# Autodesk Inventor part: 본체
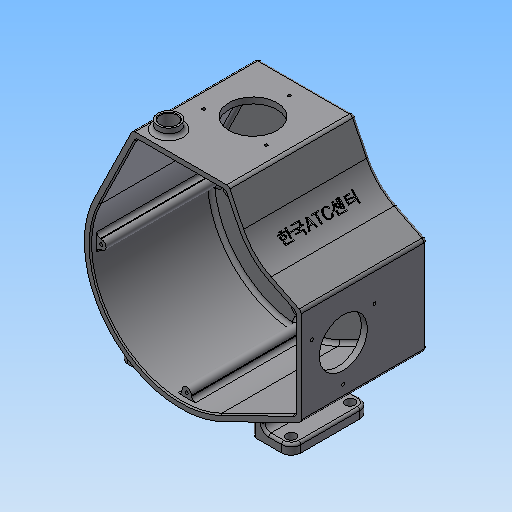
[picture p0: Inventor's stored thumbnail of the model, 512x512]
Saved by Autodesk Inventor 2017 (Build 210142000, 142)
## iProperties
Created: 2017-05
Part Number: 본체
Material: 일반
Document SubType Name: Modeling
Designer: mduedu
Density: 1 g/cm^3
Appearance: 기본값
Mass: 496.576 g
Surface Area: 1824.08 cm^2
Volume: 496.576 cm^3
Author: mduedu
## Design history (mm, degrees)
sketch "스케치1"
  geometry: L1 (-71.801, 35.28)-(-40, 100); L2 (-40, 100)-(40, 100); L3 (40, 100)-(59.768, 59.768); L4 (59.768, 59.768)-(100, 40); L5 (100, 40)-(100, -40); L6 (100, -40)-(35.28, -71.801); A1 r 80 centre (0, 0) between (-71.801, 35.28) and (35.28, -71.801); 3 further points
  constraints: 12 end point, 4 tangent, 2 midpoint, 2 point on circle, 1 centre point, 1 coincident, 1 horizontal, 1 horizontal alignment, 1 perpendicular, 1 vertical alignment
  dimensions: "d0" = 160 diameter of A1; "d2" = 100 distance from line of L2 point (0, 0); "d3" = 100 distance from line of L5 point (0, 0); "d4" = 80 distance of L1.end L2.end; "d5" = 80 distance of L4.end L5.end
extrude "돌출1" new body sketch "스케치1" distance "d6" = 5; taper "d7" = 0 deg
fillet "모깎기1" dims "d8" = 50
sketch "스케치2"
  geometry: C1 r 22 at (0, 0); 1 further point
  constraints: 1 centre point, 1 coincident
  dimensions: "d9" = 44 diameter of C1
extrude "돌출2" join sketch "스케치2" distance "d10" = 22.5; taper "d11" = 0 deg
sketch "스케치3"
  geometry: C1 r 18.5 at (0, 0); 1 further point
  constraints: 1 centre point, 1 coincident
  dimensions: "d12" = 37 diameter of C1
extrude "돌출3" cut sketch "스케치3" distance "d13" = 9; taper "d14" = 0 deg
fillet "모깎기2" dims "d15" = 3
sketch "스케치4"
  geometry: L1 (35.28, -71.801)-(100, -40) reference; L2 (100, -40)-(100, 40) reference; L3 (100, 40)-(75.073, 52.248) reference; L4 (52.248, 75.073)-(40, 100) reference; L5 (40, 100)-(-40, 100) reference; L6 (-40, 100)-(-71.801, 35.28) reference; L7 (-36.886, 95)-(36.886, 95); L8 (36.886, 95)-(47.76, 72.868); L9 (72.868, 47.76)-(95, 36.886); L10 (95, 36.886)-(95, -36.886); L11 (95, -36.886)-(33.075, -67.313); L12 (-67.313, 33.075)-(-36.886, 95); C1 r 25 at (0, 0) reference; A1 r 50 centre (97.123, 97.123) between (52.248, 75.073) and (75.073, 52.248) reference; A2 r 80 centre (0, 0) between (-71.801, 35.28) and (35.28, -71.801) reference; A3 r 55 centre (97.123, 97.123) between (47.76, 72.868) and (72.868, 47.76); A4 r 75 centre (0, 0) between (-67.313, 33.075) and (33.075, -67.313); 1 further point
  constraints: 12 end point, 4 point on circle, 2 centre point, 7 other
  dimensions: "d16" = 5 distance between parallel lines of L7 L5
extrude "돌출4" join sketch "스케치4" distance "d17" = 100; taper "d18" = 0 deg
sketch "스케치5"
  geometry: L1 (80, 0)-(0, 0) reference; C1 r 20 at (40, -45); 2 further points
  constraints: 1 centre point, 1 midpoint, 1 vertical alignment
  dimensions: "d19" = 40 diameter of C1; "d21" = 45 distance from line of C1.centre L1
extrude "돌출5" cut sketch "스케치5" stored distance "d22" = 100; taper "d23" = 0 deg
sketch "스케치6"
  geometry: L1 (0, 0)-(0, -105) reference; L2 (80, -105)-(0, -105) reference; C1 r 9 at (14, -89); 1 further point
  constraints: 1 centre point
  dimensions: "d24" = 18 diameter of C1; "d26" = 14 distance from line of C1.centre L1; "d27" = 16 distance from line of C1.centre L2
extrude "돌출6" join sketch "스케치6" distance "d28" = 7; taper "d29" = 0 deg
hole "구멍1" diameter "d32" = 14; stored, may be unused: countersink angle "d36" = 90 deg, drill point angle "d38" = 118 deg; dims "d33" = 6, "d34" = 4, "d35" = 2, "d37" = 8, "d39" = 10, "d40" = 10
sketch "스케치7"
  geometry: L1 (-105, 0)-(-105, 80) reference; L2 (0, 0)-(0, 80) reference; C1 r 20 at (-70, 40); 2 further points
  constraints: 1 centre point, 1 horizontal alignment, 1 midpoint
  dimensions: "d41" = 40 diameter of C1; "d42" = 35 distance from line of C1.centre L1
extrude "돌출7" cut sketch "스케치7" stored distance "d43" = 7; taper "d44" = 0 deg
node "작업 평면1"
sketch "스케치8"
  geometry: L1 (47.76, 72.868)-(36.886, 95) reference; L2 (36.886, 95)-(-36.886, 95) reference; L3 (-36.886, 95)-(-67.313, 33.075) reference; L4 (33.075, -67.313)-(95, -36.886) reference; L5 (95, -36.886)-(95, 36.886) reference; L6 (95, 36.886)-(72.868, 47.76) reference; L7 (95, 36.886)-(95, -36.886) reference; L8 (-36.886, 95)-(36.886, 95) reference; L9 (36.886, 95)-(47.76, 72.868) reference; L10 (-71, 4)-(-74.893, 4); L11 (-71, -4)-(-74.893, -4); L12 (-4, -71)-(-4, -74.893); L13 (4, -71)-(4, -74.893); L14 (30.394, 91)-(30.394, 95); L15 (34.394, 87)-(40.817, 87); L16 (30.394, 95)-(36.886, 95); L17 (36.886, 95)-(37.984, 92.764); L18 (91, 30.394)-(95, 30.394); L19 (87, 34.394)-(87, 40.817); L20 (87, 40.817)-(95, 36.886); L21 (95, 36.886)-(95, 30.394); C1 r 25 at (0, 0) reference; A1 r 75 centre (0, 0) between (-67.313, 33.075) and (33.075, -67.313) reference; A2 r 55 centre (97.123, 97.123) between (47.76, 72.868) and (72.868, 47.76) reference; A3 r 4 centre (-71, 0) between (-71, 4) and (-71, -4); A4 r 4 centre (0, -71) between (-4, -71) and (4, -71); A5 r 4 centre (34.394, 91) between (30.394, 91) and (34.394, 87); A6 r 75 centre (0, 0) between (-67.313, 33.075) and (33.075, -67.313) reference; A7 r 4 centre (91, 34.394) between (91, 30.394) and (87, 34.394); 1 further point
  constraints: 24 end point, 17 point on circle, 14 tangent, 5 point on line, 4 centre point, 3 equal radius, 3 perpendicular, 3 vertical, 2 collinear, 2 horizontal, 1 horizontal alignment, 1 parallel, 1 vertical alignment
  dimensions: "d46" = 8 diameter of A3
extrude "돌출8" join sketch "스케치8" stored distance "d49" = 7; taper "d50" = 0 deg
node "작업 평면2"
sketch "스케치9"
  geometry: L1 (71.801, 0)-(71.801, 105) reference; L2 (71.801, 0)-(-35.28, 0) reference; L3 (-35.28, 0)-(-35.28, 105) reference; L4 (71.801, 105)-(-35.28, 105) reference; L5 (40, 0)-(40, 105) reference; L6 (71.801, 52.5)-(-35.28, 52.5); L7 (71.801, 20)-(40, 20); L8 (40, 20)-(40, 85); L9 (40, 85)-(71.801, 85); L10 (71.801, 85)-(71.801, 20); 1 further point
  constraints: 10 end point, 2 midpoint, 2 parallel, 2 point on line, 1 horizontal, 1 perpendicular, 1 other
  dimensions: "d52" = 20 distance between parallel lines of L7 L2
extrude "돌출9" join sketch "스케치9" distance "d53" = 8; taper "d54" = 0 deg
fillet "모깎기3" dims "d55" = 8
sketch "스케치10"
  geometry: C1 r 4 at (-63.801, -28); C2 r 4 at (-63.801, -77); A1 r 8 centre (-63.801, -28) between (-63.801, -20) and (-71.801, -28) reference; A2 r 8 centre (-63.801, -77) between (-71.801, -77) and (-63.801, -85) reference; 1 further point
  constraints: 2 centre point, 2 coincident, 1 equal radius
  dimensions: "d56" = 8 diameter of C1
extrude "돌출10" cut sketch "스케치10" stored distance "d57" = 50.5; taper "d58" = 0 deg
sketch "스케치11"
  geometry: L1 (-63.801, -20)-(-40, -20) reference; L2 (-40, -20)-(-40, -85) reference; L3 (-40, -85)-(-63.801, -85) reference; L4 (-71.801, -77)-(-71.801, -28) reference; L5 (71.801, -77)-(71.801, -28) reference; L6 (40, -85)-(63.801, -85) reference; L7 (40, -20)-(40, -85) reference; L8 (63.801, -20)-(40, -20) reference; L9 (-40, -85)-(-48, -85); L10 (-48, -85)-(-48, -20); L11 (-48, -20)-(-40, -20); L12 (-40, -20)-(-40, -85); L13 (40, -85)-(48, -85); L14 (48, -85)-(48, -20); L15 (48, -20)-(40, -20); L16 (40, -20)-(40, -85); C1 r 4 at (-63.801, -28) reference; C2 r 4 at (-63.801, -77) reference; C3 r 4 at (63.801, -28) reference; C4 r 4 at (63.801, -77) reference; A1 r 8 centre (-63.801, -28) between (-63.801, -20) and (-71.801, -28) reference; A2 r 8 centre (-63.801, -77) between (-71.801, -77) and (-63.801, -85) reference; A3 r 8 centre (63.801, -28) between (71.801, -28) and (63.801, -20) reference; A4 r 8 centre (63.801, -77) between (63.801, -85) and (71.801, -77) reference; 1 further point
  constraints: 16 end point, 4 parallel, 2 horizontal, 2 perpendicular, 2 point on line
  dimensions: "d59" = 8 distance of L10.end L11.end; "d61" = 8 distance of L14.end L15.end
extrude "돌출11" join sketch "스케치11" stored distance "d62" = 5; taper "d63" = 0 deg
fillet "모깎기4" dims "d64" = 5
fillet "모깎기5" dims "d65" = 2
fillet "모깎기6" dims "d66" = 2
fillet "모깎기8" dims "d68" = 2
fillet "모깎기9" dims "d70" = 3, "d101" = 1
fillet "모깎기10" dims "d71" = 3
fillet "모깎기11" dims "d72" = 3
fillet "모깎기12" dims "d73" = 3
fillet "모깎기13" dims "d76" = 3
chamfer "모따기1" distance "d77" = 0.5; stored, may be unused: second distance "d78" = 2, angle "d79" = 45 deg
chamfer "모따기2" distance "d87" = 1; stored, may be unused: second distance "d88" = 2, angle "d89" = 45 deg
chamfer "모따기3" distance "d90" = 1; stored, may be unused: second distance "d91" = 2, angle "d92" = 45 deg
sketch "스케치14"
  geometry: 3 further points
  constraints: 3 other
hole "구멍2" sketch "스케치14" at (-55.375, -40), (-3.414, -40), (-29.394, -85) diameter "d93" = 2.459; stored, may be unused: countersink angle "d97" = 90 deg, drill point angle "d99" = 0 deg; dims "d94" = 6, "d95" = 4, "d96" = 2, "d98" = 8
sketch "스케치15"
  geometry: 3 further points
  constraints: 3 other
hole "구멍4" sketch "스케치15" at (-55.981, -14.394), (-4.019, -14.394), (-30, -59.394) diameter "d102" = 2.459; stored, may be unused: countersink angle "d106" = 90 deg, drill point angle "d108" = 0 deg; dims "d103" = 6, "d104" = 4, "d105" = 2, "d107" = 8
sketch "스케치16"
  geometry: 4 further points
  constraints: 4 other
hole "구멍6" sketch "스케치16" at (0, -71), (91, 34.394), (34.394, 91), (-71, 0) diameter "d109" = 2.459; stored, may be unused: countersink angle "d113" = 90 deg, drill point angle "d115" = 120 deg; dims "d110" = 8.5, "d111" = 4, "d112" = 2, "d114" = 10
node "작업 평면4"
sketch "스케치17"
  geometry: 2 further points
  constraints: 1 horizontal alignment, 1 other
  dimensions: "d116" = 52.5 distance of point (0, 16.14) point (52.5, 16.14)
feature "엠보싱2" sketch "스케치17" dims "d117" = 0.5, "d118" = 0
node "솔리드1"
mirror "대칭1"
node "투영된 루프1"
node "투영된 루프2"
node "투영된 루프3"
node "투영된 루프4"
node "투영된 루프5"
other parameters: "d45" = 95
